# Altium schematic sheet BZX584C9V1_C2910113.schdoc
size 127 x 101 mm
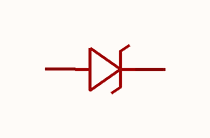
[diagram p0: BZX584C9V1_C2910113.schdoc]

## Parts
U?  bzx584c9v1_c2910113  [SOD-523_L1.2-W0.8-LS1.6-FD]  (value not drawn)

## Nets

Not connected (* = marked no-connect by the designer): U? 1(A) 2(K)

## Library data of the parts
U? = bzx584c9v1_c2910113: 二极管配置:1个独立式;稳压值(标称值):9.1V;稳压值(范围):8.5V~9.6V;耗散功率(Pd):150mW;; Manufacturer: CJ(江苏长电/长晶); AddInBom: yes; ModelId: 8f56a03db567494d8f4c9d12aa52a741; ModelName: SOD-523_L1.2-W0.8-H0.7-LS1.6; ModelTransform: 62.992,31.496,0,0,0,0,0,0,0; Diode Configuration: 1个独立式; Zener Voltage(Nom): 9.1V; Reverse Leakage Current (Ir): 500nA@6V; Pd - Power Dissipation: 150mW; Impedance(Zzt): 15Ω; Impedance(Zzk): 100Ω; Operating Junction Temperature Range: -55℃~+150℃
